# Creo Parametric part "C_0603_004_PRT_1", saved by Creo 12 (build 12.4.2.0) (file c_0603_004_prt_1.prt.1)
Units: Custom; MM, KILOGRAM, SECS

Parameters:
  PTC_WM_ITERATION = "0"
  PTC_WM_VERSION = "-.0"
  PTC_WM_LIFECYCLE_STATE = "In Work"
  PTC_WM_LIFECYCLE = "MO_CADDocument"
  PTC_WM_CREATED_BY = "Maximilian Roepper (Z0017RMS: MO)"
  PTC_WM_CREATED_ON = "18-Sep-26 11:36:42 AM"
  PTC_WM_MODIFIED_BY = "Maximilian Roepper (Z0017RMS: MO)"
  PTC_WM_MODIFIED_ON = "18-Sep-26 11:36:46 AM"
  PDMLINKNUMBER = "PDM000071455165"
  PTC_WM_NAME = "c_0603_004_prt_1.prt"
  PTC_WM_NUMBER = "PDM000071455165"

Other parameters: WEIGHT, WEIGHT_FACTOR, WEIGHT_ADD, _MASS_TEMP, _DIFF_TEMP, MC_ERRORS, SUPPLIER

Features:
  1. coordinate system
  2. datum plane "PRT_YZ"
  3. datum plane "PRT_XY"
  4. datum plane "PRT_XZ"
  5. coordinate system
  6. datum axis
  7. datum axis
  8. datum axis
  9. coordinate system
  10. imported feature
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
Other named items: PRT, SIEMENS_MO, DRW_VIEW_ORG, PRT_X, PRT_Y, PRT_Z, CS0, ROUGH_GROB

Layers: 00_STD_CSYS-KSYS, 01_STD_PLANES-EBENEN, 02_STD_AXES-ACHSEN, 03_STD_CSYS-KSYS, 24_IMPORT_FEAT-IMPORT_KE

Surfaces: 16 plane, 12 cylinder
